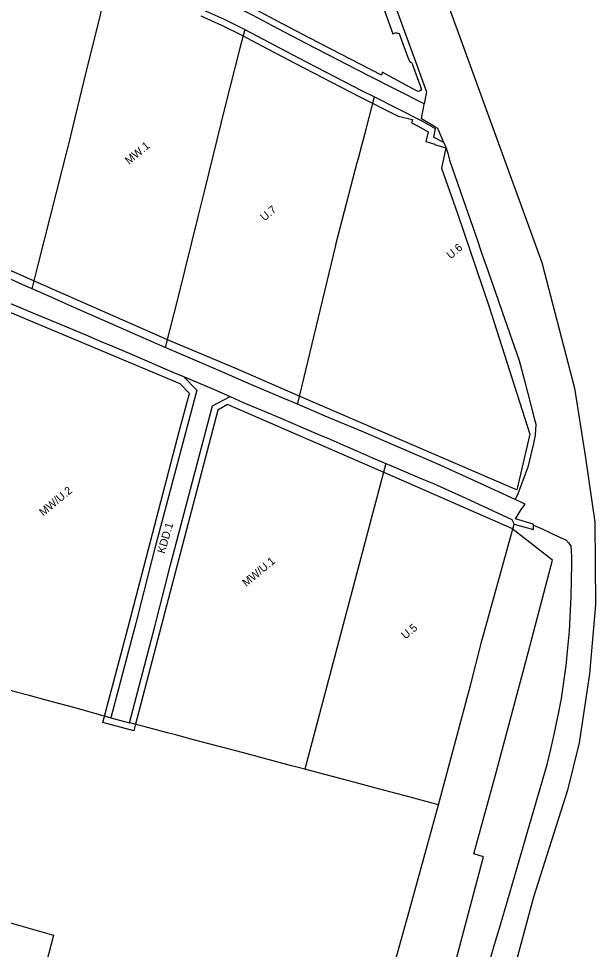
# Model space of a CAD drawing. Extents: x 7418616 to 7420822, y 5550745 to 5553106.
# Drawn here: x 7420462 to 7420822, y 5551038 to 5551619 of the extents above; entities that cross this region are included whole.
import ezdxf

# ---------------------------------------------------------------- set-up
doc = ezdxf.new("R2010")
doc.units = 0
for name, color, linetype in [('granica obszaru objętego planem', 7, 'Continuous'), ('linie rozgraniczające', 7, 'Continuous'), ('nieprzekraczalne linie zabudowy', 7, 'Continuous'), ('przeznaczenia terenów', 7, 'Continuous')]:
    doc.layers.add(name, color=color, linetype=linetype)

msp = doc.modelspace()

# ---------------------------------------------------------------- linework, layer by layer
at = {"layer": 'granica obszaru objętego planem'}
msp.add_lwpolyline([(7420611.64, 5551954.27), (7420788.95, 5551466.82), (7420809.37, 5551388.21), (7420816.18, 5551344.71), (7420822.14, 5551304.48), (7420822.4, 5551252.86), (7420818.63, 5551209.81), (7420812.35, 5551166.69), (7420805.01, 5551137.04), (7420783.83, 5551070.13), (7420770.23, 5551020.07)], dxfattribs=at)
at = {"layer": 'linie rozgraniczające'}
for p, q in [((7420691.51, 5551341.21), (7420640.87, 5551150.11)), ((7420519.65, 5551182.3), (7420531.25, 5551179.22))]:
    msp.add_line(p, q, dxfattribs=at)
for points in [[(7420611.64, 5551954.27), (7420788.95, 5551466.82), (7420809.37, 5551388.21), (7420816.18, 5551344.71), (7420822.14, 5551304.48), (7420822.4, 5551252.86), (7420818.63, 5551209.81), (7420812.35, 5551166.69), (7420805.01, 5551137.04), (7420783.83, 5551070.13), (7420770.23, 5551020.07)], [(7420657.64, 5551737.41), (7420657.66, 5551737.35), (7420662.48, 5551723.99), (7420664.17, 5551719.3), (7420670.77, 5551701.04), (7420676.02, 5551686.48), (7420677.51, 5551682.36), (7420680.54, 5551674.12), (7420683.66, 5551665.32), (7420689.62, 5551648.81), (7420696.56, 5551629.55), (7420703.22, 5551611.13), (7420709.97, 5551592.42), (7420716.81, 5551573.46), (7420715.46, 5551565.97)], [(7420470.48, 5551450.29), (7420474.34, 5551465.31), (7420489.31, 5551524.58), (7420494.68, 5551545.81), (7420494.71, 5551545.91), (7420503.09, 5551580.48), (7420513.15, 5551621.48), (7420518.37, 5551645.27)], [(7420518.37, 5551645.27), (7420533.91, 5551640.55), (7420552.06, 5551634.41), (7420565.64, 5551629.41), (7420577.38, 5551624.71), (7420590.52, 5551618.8), (7420603.34, 5551612.34)], [(7420715.46, 5551565.97), (7420680.95, 5551583.37), (7420641.65, 5551603.74), (7420620.61, 5551614.78), (7420608.14, 5551621.35), (7420594.81, 5551628.06), (7420581.33, 5551634.12), (7420569.37, 5551638.91), (7420563.98, 5551640.89)], [(7420603.34, 5551612.34), (7420600.26, 5551600.72), (7420590.94, 5551563.95), (7420578.43, 5551512.74), (7420574.28, 5551496.07), (7420561.72, 5551445.55), (7420553.73, 5551413.63)], [(7420603.34, 5551612.34), (7420636.93, 5551594.7), (7420676.28, 5551574.3), (7420684.34, 5551570.23)], [(7420635.81, 5551378.45), (7420636.47, 5551378.69), (7420650.67, 5551437.55), (7420660.15, 5551477.46), (7420660.26, 5551477.93), (7420673.64, 5551529.3), (7420674.33, 5551532.04), (7420679.36, 5551550.86), (7420684.34, 5551570.23)], [(7420684.34, 5551570.23), (7420713.51, 5551555.54), (7420713.51, 5551555.51), (7420722.33, 5551550.58), (7420721.37, 5551545.04), (7420722.83, 5551544.53), (7420727.7, 5551541.87)], [(7420727.7, 5551541.87), (7420724.06, 5551550.5), (7420722.46, 5551551.36), (7420713.76, 5551556.55), (7420713.69, 5551556.59), (7420714.39, 5551560.04), (7420715.15, 5551564.24), (7420715.46, 5551565.97)], [(7420727.7, 5551541.87), (7420729.18, 5551538.15), (7420730.3, 5551535.05), (7420731.21, 5551530.75), (7420737.9, 5551511.5), (7420744.36, 5551492.96), (7420748.48, 5551481.11), (7420751.13, 5551473.47), (7420755.39, 5551461.24), (7420761.63, 5551443.3), (7420764.21, 5551435.87), (7420774.72, 5551405.64), (7420778.28, 5551392.11), (7420784.02, 5551370.34), (7420785.2, 5551365.85), (7420784.87, 5551358.91), (7420783.51, 5551352.92), (7420780.23, 5551338.94), (7420774.05, 5551322.23), (7420772.3, 5551318.72)], [(7420470.48, 5551450.29), (7420466.61, 5551451.98), (7420452.83, 5551458.21), (7420443.04, 5551462.02), (7420433.08, 5551466.52), (7420417.91, 5551473.01), (7420401.57, 5551479.53), (7420389.11, 5551484.32), (7420380.2, 5551487.87), (7420358.35, 5551496), (7420345.61, 5551500.39), (7420344.48, 5551500.75)], [(7420553.73, 5551413.63), (7420519.42, 5551428.62), (7420495.29, 5551439.29), (7420480.53, 5551445.89), (7420470.48, 5551450.29)], [(7420454.26, 5551442), (7420456.01, 5551441.5), (7420474.85, 5551433.74), (7420485.44, 5551429.34), (7420494.4, 5551425.53), (7420504.04, 5551421.55), (7420514.44, 5551417.1), (7420518.17, 5551415.56), (7420524.61, 5551412.91), (7420531.08, 5551410.21), (7420558.49, 5551398.24), (7420565.01, 5551395.49)], [(7420635.81, 5551378.45), (7420627.81, 5551381.89), (7420607.23, 5551390.49), (7420588.67, 5551398.76), (7420563.33, 5551409.44), (7420553.73, 5551413.63)], [(7420565.01, 5551395.49), (7420573.31, 5551387.01), (7420547.24, 5551288.18), (7420545.1, 5551280.05), (7420535.28, 5551241.45), (7420519.65, 5551182.3)], [(7420565.01, 5551395.49), (7420583.87, 5551387.54), (7420594.17, 5551382.95)], [(7420531.25, 5551179.22), (7420546.9, 5551238.44), (7420556.72, 5551277.04), (7420583.12, 5551377.2), (7420594.17, 5551382.95)], [(7420594.17, 5551382.95), (7420602.46, 5551379.26), (7420623.02, 5551370.67), (7420648.95, 5551359.53), (7420654.7, 5551357.14), (7420655.16, 5551356.94), (7420664.65, 5551352.91), (7420673.77, 5551348.79), (7420683.18, 5551344.76), (7420691.51, 5551341.21)], [(7420772.3, 5551318.72), (7420748.8, 5551329.53), (7420723.66, 5551340.96), (7420697.94, 5551352.08), (7420677.78, 5551360.77), (7420653.67, 5551370.78), (7420635.81, 5551378.45)], [(7420691.51, 5551341.21), (7420693.64, 5551340.31), (7420714.06, 5551331.69), (7420721.19, 5551328.68), (7420743.73, 5551318.43), (7420770.25, 5551306.24), (7420771.63, 5551303.27)], [(7420783.65, 5551302.73), (7420783.62, 5551303.3), (7420772.58, 5551306.7), (7420776.48, 5551312.98), (7420778.53, 5551315.86), (7420772.3, 5551318.72)], [(7420724.45, 5551127.9), (7420735.31, 5551168.23), (7420744.64, 5551203.38), (7420750.79, 5551227.84), (7420751.47, 5551230.55), (7420751.8, 5551231.73), (7420771.63, 5551303.27)], [(7420783.65, 5551302.73), (7420789.47, 5551300.05), (7420800.08, 5551295.19), (7420804.01, 5551293.39), (7420805.69, 5551291.56), (7420807, 5551289.65), (7420807.42, 5551282.95), (7420807.4, 5551278.34), (7420807.05, 5551258.25), (7420805.99, 5551236.38), (7420804.84, 5551223.84), (7420804.06, 5551216.87), (7420803.86, 5551215.04), (7420801.09, 5551194.29), (7420799.44, 5551185.84), (7420798.72, 5551182.77), (7420796.46, 5551171.82), (7420794.36, 5551162.62), (7420792.22, 5551153.91), (7420791.99, 5551152.84), (7420781.22, 5551115.71), (7420770.2, 5551077.63), (7420762.88, 5551052.76), (7420759.25, 5551040.43), (7420755.39, 5551027.32)], [(7420771.63, 5551303.27), (7420783.8, 5551299.89), (7420783.65, 5551302.73)], [(7420436.76, 5551205.18), (7420446.47, 5551202.49), (7420456.79, 5551199.59), (7420460.64, 5551198.52), (7420467.79, 5551196.53), (7420478.23, 5551193.62), (7420488.45, 5551190.91), (7420498.58, 5551188.31), (7420519.65, 5551182.3)], [(7420640.87, 5551150.11), (7420632.62, 5551152.3), (7420622.53, 5551154.98), (7420612.61, 5551157.61), (7420602.48, 5551160.3), (7420592.23, 5551163.03), (7420581.68, 5551165.82), (7420571.37, 5551168.57), (7420560.84, 5551171.36), (7420555.19, 5551172.86), (7420540.35, 5551176.8), (7420531.25, 5551179.22)], [(7420724.45, 5551127.9), (7420703.48, 5551133.49), (7420693.96, 5551136.01), (7420684.64, 5551138.49), (7420674.6, 5551141.15), (7420664.5, 5551143.83), (7420643.1, 5551149.52), (7420640.87, 5551150.11)], [(7420576.06, 5550787.51), (7420578.37, 5550796.59), (7420580.84, 5550806.25), (7420578.99, 5550806.68), (7420586.68, 5550836.57), (7420588.69, 5550837.04), (7420596.17, 5550838.79), (7420596.67, 5550840.46), (7420633.7, 5550831.52), (7420633.88, 5550832.15), (7420635.69, 5550832.49), (7420652.27, 5550896.33), (7420655.83, 5550907.98), (7420658.29, 5550916.34), (7420664.52, 5550939.44), (7420670.58, 5550937.72), (7420671.79, 5550937.38), (7420686.67, 5550991.47), (7420691.29, 5551008.28), (7420706.19, 5551062.05), (7420712.87, 5551086.14), (7420724.45, 5551127.9)], [(7420401.62, 5551069.56), (7420411.19, 5551066.74), (7420421.57, 5551063.94), (7420432.94, 5551060.93), (7420442.75, 5551058.24), (7420453.49, 5551055.26), (7420463.38, 5551052.22), (7420483.93, 5551046.39), (7420448.44, 5550910.56), (7420443.54, 5550891.79)]]:
    msp.add_lwpolyline(points, dxfattribs=at)
at = {"layer": 'nieprzekraczalne linie zabudowy'}
for points in [[(7420689.3, 5551628.15), (7420695.9, 5551609.77), (7420697.45, 5551610.32), (7420698.37, 5551610.32), (7420699, 5551610.15), (7420699.59, 5551609.79), (7420700.11, 5551609.2), (7420702.21, 5551603.53), (7420705.1, 5551595.52), (7420706.38, 5551592.14), (7420706.64, 5551592.05), (7420706.84, 5551592.05), (7420707.13, 5551591.98), (7420707.52, 5551591.72), (7420707.79, 5551591.39), (7420707.96, 5551590.96), (7420713.65, 5551575.47), (7420713.52, 5551574.82), (7420713.17, 5551574.2), (7420712.42, 5551573.77), (7420711.81, 5551573.59), (7420711.29, 5551573.77), (7420708.71, 5551575.08), (7420689.27, 5551585.66), (7420688.78, 5551583.9), (7420682.77, 5551586.93), (7420643.51, 5551607.28), (7420622.47, 5551618.32), (7420609.97, 5551624.91)], [(7420575.82, 5551621.03), (7420588.8, 5551615.19), (7420601.59, 5551608.75), (7420614, 5551602.21), (7420635.06, 5551591.16), (7420674.44, 5551570.75), (7420699.19, 5551558.27), (7420708.12, 5551556.11), (7420707.5, 5551554.09), (7420711.35, 5551552.14), (7420717.9, 5551548.47), (7420716.49, 5551542.41), (7420722.01, 5551540.83), (7420721.94, 5551540.48), (7420729.03, 5551538.53), (7420726.26, 5551525.73), (7420736.26, 5551497.35), (7420756.07, 5551439.16), (7420781.48, 5551359.48), (7420773.34, 5551324.65), (7420771.16, 5551325.51), (7420638.34, 5551382.85), (7420597.31, 5551400.73), (7420556.63, 5551417.82), (7420472.51, 5551454.93), (7420429.6, 5551473.97)], [(7420723.51, 5550986.46), (7420752.47, 5551095.47), (7420746.43, 5551097.17), (7420760.21, 5551147.18), (7420780.65, 5551223.67), (7420795.62, 5551280.83), (7420770.13, 5551300.65), (7420689.35, 5551335.99), (7420592.51, 5551377.97), (7420586.54, 5551374.47), (7420554.55, 5551252.27), (7420535.12, 5551178.2), (7420534.04, 5551174.16), (7420514.73, 5551179.31), (7420530.25, 5551238.1), (7420562.35, 5551361.15), (7420568.88, 5551384.83), (7420562.96, 5551390.99), (7420452.94, 5551437.15)]]:
    msp.add_lwpolyline(points, dxfattribs=at)

# ---------------------------------------------------------------- texts
at = {"layer": 'przeznaczenia terenów'}
for s, rotation, p in [('MW.1', 39.84394, (7420531.08, 5551527.79)), ('U.7', 39.84394, (7420615.65, 5551492.34)), ('U.6', 39.84394, (7420731.96, 5551468.66)), ('MW/U.2', 39.84394, (7420477.49, 5551308.03)), ('KDD.1', 73.83273, (7420553.29, 5551284.55)), ('MW/U.1', 39.84394, (7420604.31, 5551263.94)), ('U.5', 39.84394, (7420703.72, 5551231.1))]:
    msp.add_text(s, height=5, rotation=rotation, dxfattribs=at).set_placement(p)

doc.saveas('drawing.dxf')
